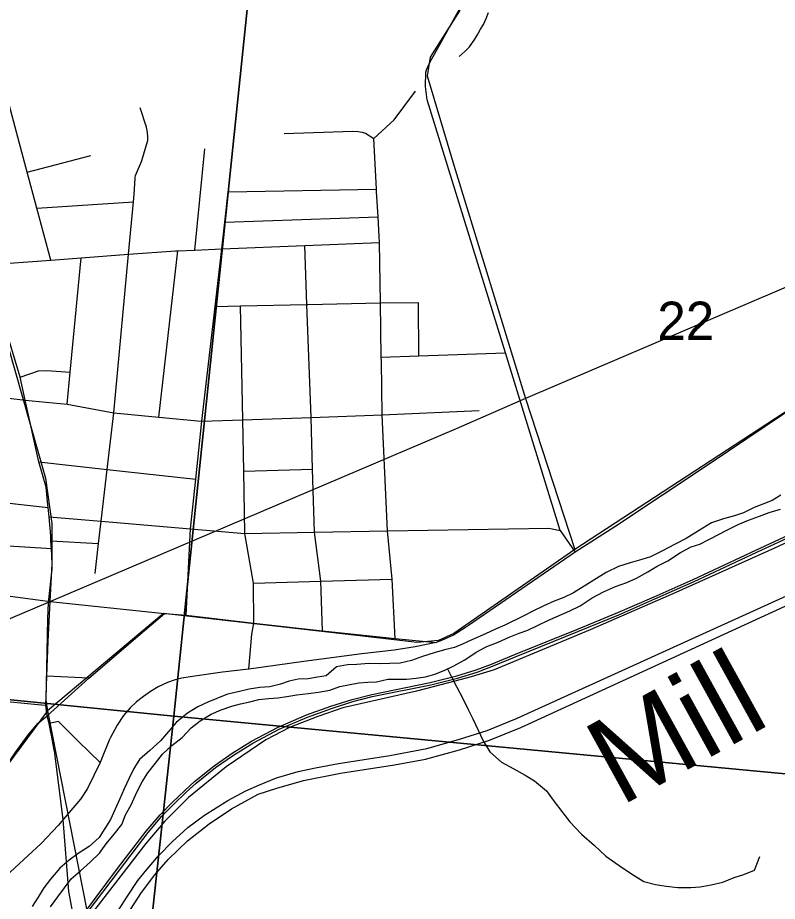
# Model space of a CAD drawing. Extents: x -8.2 to 38.5, y -0.1 to 21.9.
# Drawn here: x 5.667 to 6.498, y 17.89 to 18.858 of the extents above; entities that cross this region are included whole.
import ezdxf

# ---------------------------------------------------------------- set-up
doc = ezdxf.new("R2010")
doc.units = 0
for name, color, linetype in [('GM_X_Adjacent_County_Text', 7, 'Continuous'), ('GM_X_Airport_Location_Class_3', 7, 'Continuous'), ('GM_X_County_Road_Text', 7, 'Continuous'), ('GM_X_Minor_River', 7, 'Continuous'), ('GM_X_Minor_River_Text', 7, 'Continuous'), ('GM_X_State_Location', 7, 'Continuous'), ('GM_X_Township_Subdivision_Text', 7, 'Continuous'), ('GM_X_Township_Text', 7, 'Continuous'), ('GM_X_US_Location', 7, 'Continuous')]:
    doc.layers.add(name, color=color, linetype=linetype)

msp = doc.modelspace()

# ---------------------------------------------------------------- linework, layer by layer
at = {"layer": 'GM_X_Adjacent_County_Text'}
for points in [[(5.93961, 19.07468), (5.83799, 18.09248), (4.83948, 18.19258), (4.94575, 19.17922)], [(5.93961, 19.07468), (6.95853, 18.98963), (6.85894, 17.99642), (5.83799, 18.09248)], [(6.85894, 17.99642), (6.75364, 16.98553), (5.7325, 17.12325), (5.83799, 18.09248)]]:
    msp.add_lwpolyline(points, close=True, dxfattribs=at)
msp.add_lwpolyline([(4.75441, 17.38985), (4.83948, 18.19258), (5.83799, 18.09248), (5.7325, 17.12325), (5.03564, 17.19219)], dxfattribs=at)
at = {"layer": 'GM_X_Airport_Location_Class_3'}
for points in [[(5.70343, 18.07485), (5.7014, 18.08446), (5.69927, 18.09317), (5.69796, 18.10419), (5.69884, 18.13649), (5.70025, 18.17468), (5.70267, 18.21835), (5.70495, 18.25962), (5.704, 18.27618), (5.70351, 18.28476), (5.7032, 18.2901), (5.70136, 18.3109), (5.70045, 18.32113), (5.69985, 18.32787), (5.69824, 18.34352), (5.69005, 18.37104), (5.67517, 18.43875), (5.6697, 18.46371), (5.63265, 18.58676)], [(5.70717, 18.05558), (5.70404, 18.07196), (5.70343, 18.07485)], [(5.7594, 17.81549), (5.75592, 17.81917), (5.74934, 17.82772), (5.7386, 17.84505), (5.73114, 17.86457), (5.72675, 17.88124), (5.72302, 17.90054), (5.71691, 17.97934), (5.70735, 18.05462), (5.70717, 18.05558)]]:
    msp.add_lwpolyline(points, dxfattribs=at)
at = {"layer": 'GM_X_Minor_River'}
for points in [[(6.15032, 18.81505), (6.15695, 18.82096), (6.16163, 18.8254), (6.16757, 18.834), (6.17076, 18.83962), (6.17357, 18.84487), (6.17675, 18.85011), (6.17997, 18.8565), (6.18243, 18.86328)], [(6.5023, 18.33466), (6.49266, 18.32885), (6.48269, 18.32494), (6.4731, 18.32103), (6.46156, 18.31527), (6.45162, 18.31213), (6.43939, 18.30867), (6.42638, 18.30447), (6.4121, 18.29575), (6.39859, 18.28701), (6.38666, 18.28088), (6.37204, 18.27331), (6.35973, 18.26719), (6.35016, 18.26404), (6.33755, 18.26059), (6.32454, 18.25639), (6.31109, 18.24992), (6.29759, 18.24156), (6.27521, 18.22775), (6.26483, 18.22272), (6.25409, 18.21845), (6.24295, 18.21344), (6.23143, 18.20807), (6.22027, 18.2023), (6.20027, 18.19222), (6.18991, 18.18794), (6.17915, 18.18292), (6.16417, 18.17612), (6.15457, 18.17183), (6.14498, 18.16791), (6.13429, 18.16517), (6.12283, 18.16207), (6.1102, 18.15786), (6.09794, 18.15364), (6.08572, 18.15055), (6.07434, 18.15049), (6.06334, 18.15003), (6.05121, 18.15036), (6.03829, 18.1492), (6.02804, 18.14872), (6.01585, 18.14678), (6.00457, 18.13684), (5.99505, 18.1352), (5.98514, 18.13357), (5.97413, 18.13312), (5.96422, 18.13111), (5.95464, 18.12758), (5.94319, 18.12485), (5.93217, 18.12402), (5.92036, 18.12206), (5.90853, 18.11935), (5.8967, 18.11664), (5.87522, 18.10812), (5.86408, 18.10273), (5.85289, 18.09582), (5.84046, 18.08553), (5.83223, 18.07588), (5.82322, 18.0655), (5.81155, 18.05519), (5.80028, 18.04524), (5.79431, 18.03516), (5.78868, 18.02392), (5.78345, 18.01305), (5.77857, 18.00142), (5.77373, 17.99092), (5.76848, 17.97967), (5.76251, 17.96958), (5.75617, 17.95988), (5.74528, 17.94993)], [(5.71822, 17.90473), (5.7257, 17.9144), (5.73581, 17.92323), (5.74631, 17.93282), (5.75645, 17.94279), (5.76394, 17.95284), (5.77258, 17.96361), (5.78122, 17.97401), (5.78492, 17.98453), (5.79129, 17.99537), (5.79777, 18.01), (5.80339, 18.02086), (5.80934, 18.03057), (5.81799, 18.04134), (5.82547, 18.05101), (5.83559, 18.0606), (5.84722, 18.06939), (5.85698, 18.07976), (5.86668, 18.08747), (5.87864, 18.09473), (5.88978, 18.09974), (5.90126, 18.1036), (5.91081, 18.106), (5.92111, 18.10837), (5.93104, 18.11076), (5.94169, 18.11198), (5.95195, 18.11284), (5.96147, 18.1141), (5.97252, 18.11608), (5.98508, 18.11763), (5.99611, 18.11884), (6.00868, 18.12116), (6.01979, 18.12503), (6.03085, 18.12738), (6.04038, 18.12902), (6.05026, 18.12989), (6.05975, 18.13039), (6.07234, 18.13308), (6.0822, 18.13319), (6.09244, 18.13329), (6.10309, 18.13413), (6.11337, 18.13575), (6.12368, 18.1385), (6.13366, 18.14279), (6.14365, 18.14745), (6.15636, 18.15431), (6.16873, 18.1627), (6.18065, 18.16883), (6.19293, 18.17381), (6.20483, 18.17918), (6.21595, 18.18343), (6.22553, 18.18696), (6.23667, 18.19236), (6.24743, 18.19737), (6.27124, 18.20811), (6.28277, 18.21349), (6.29591, 18.22224), (6.30822, 18.22874), (6.32127, 18.23446), (6.33392, 18.23904), (6.34428, 18.24369), (6.35661, 18.25057), (6.36702, 18.25674), (6.37857, 18.26288), (6.39248, 18.27199), (6.40402, 18.27812), (6.41358, 18.2809), (6.42512, 18.28666), (6.44321, 18.29641), (6.45552, 18.30253), (6.46702, 18.30715), (6.47891, 18.31176), (6.48963, 18.31564), (6.50188, 18.31948)], [(6.13731, 18.14449), (6.14159, 18.13657), (6.14775, 18.12425), (6.15393, 18.11269), (6.16008, 18.09998), (6.16515, 18.08959), (6.17635, 18.06574), (6.18366, 18.05377), (6.19668, 18.04242), (6.21018, 18.03486), (6.22255, 18.0281), (6.23266, 18.02176), (6.24569, 18.0108), (6.25305, 18.00073), (6.26373, 17.98677), (6.27147, 17.97708), (6.28406, 17.96345), (6.2982, 17.95094), (6.31084, 17.93922), (6.32541, 17.92898), (6.33887, 17.9199), (6.35234, 17.91158), (6.36518, 17.90823), (6.37692, 17.90642), (6.38942, 17.90497), (6.40386, 17.905), (6.41415, 17.90589), (6.42597, 17.90789), (6.43897, 17.91099), (6.45125, 17.91602), (6.46197, 17.91918), (6.47348, 17.92384), (6.47917, 17.93892)], [(5.74528, 17.94993), (5.73331, 17.94229), (5.72324, 17.93497), (5.71314, 17.92613), (5.70295, 17.91426), (5.69585, 17.90458), (5.6895, 17.89451), (5.68276, 17.88406)], [(5.70285, 17.88389), (5.71112, 17.89468), (5.71822, 17.90473)]]:
    msp.add_lwpolyline(points, dxfattribs=at)
at = {"layer": 'GM_X_State_Location'}
for points in [[(5.77758, 17.88024), (5.78712, 17.89559), (5.79863, 17.91259), (5.80828, 17.92477), (5.82101, 17.93979), (5.83603, 17.95514), (5.85314, 17.97061), (5.87156, 17.98431), (5.89697, 18.00027), (5.91663, 18.01085), (5.93155, 18.01732), (5.95019, 18.02522), (5.97421, 18.03191), (5.99307, 18.03618), (6.01818, 18.04068), (6.07444, 18.04945), (6.11502, 18.05735), (6.14967, 18.06711), (6.18092, 18.07709), (6.21295, 18.08992), (6.51657, 18.22815)], [(6.49366, 18.20681), (6.52072, 18.21922)], [(5.75024, 17.8086), (5.75592, 17.81917), (5.78641, 17.87488), (5.80242, 17.89944), (5.81712, 17.91896), (5.83159, 17.93563), (5.85287, 17.95603), (5.87655, 17.97467), (5.90112, 17.99134), (5.93014, 18.00732), (5.95069, 18.01393), (5.97986, 18.02205), (6.02021, 18.03038), (6.07943, 18.03937), (6.11343, 18.04551), (6.15049, 18.05582), (6.18339, 18.06635), (6.21761, 18.08017), (6.49366, 18.20681)]]:
    msp.add_lwpolyline(points, dxfattribs=at)
at = {"layer": 'GM_X_Township_Subdivision_Text'}
for p, q in [((6.05974, 18.66986), (6.05669, 18.72507)), ((5.86085, 18.60307), (5.87178, 18.71378)), ((5.67743, 18.68846), (5.74703, 18.70664)), ((5.89757, 18.66673), (6.05974, 18.66986)), ((5.68803, 18.64905), (5.7937, 18.65591)), ((5.89376, 18.6337), (6.06143, 18.63934)), ((5.82139, 18.42013), (5.84218, 18.60232)), ((6.10597, 18.48713), (6.10586, 18.54549)), ((6.06604, 18.42255), (6.17227, 18.42724)), ((5.91442, 18.36093), (5.98984, 18.3632)), ((5.62311, 18.2814), (5.704, 18.27618)), ((5.70351, 18.28476), (5.75566, 18.28157)), ((5.74498, 18.13411), (5.69884, 18.13649))]:
    msp.add_line(p, q, dxfattribs=at)
for points in [[(6.12044, 18.81232), (6.12338, 18.81765), (6.15279, 18.87094), (6.1531, 18.88078), (6.15144, 18.893), (6.13467, 18.99904), (6.13099, 19.01927), (6.11813, 19.05226), (6.08483, 19.12819), (6.08404, 19.13227), (6.0842, 19.13477), (6.08477, 19.14768), (6.09534, 19.20706), (6.09829, 19.21858)], [(5.70338, 18.59204), (5.68803, 18.64905), (5.67743, 18.68846), (5.66422, 18.73755), (5.66233, 18.74455), (5.62818, 18.87142), (5.62675, 18.87487), (5.62511, 18.87714), (5.6212, 18.87997), (5.61669, 18.88162), (5.60648, 18.88304), (5.59396, 18.88377), (5.58965, 18.88366), (5.58108, 18.88183), (5.57089, 18.87958), (5.56302, 18.87704), (5.55397, 18.87266), (5.54954, 18.87021), (5.52968, 18.85273)], [(6.26095, 18.29608), (6.22512, 18.41204), (6.20089, 18.49045), (6.11529, 18.76739), (6.11338, 18.78225), (6.11376, 18.79782), (6.11439, 18.80023), (6.11701, 18.8061), (6.12044, 18.81232)], [(5.9586, 18.73075), (6.03382, 18.73309), (6.0396, 18.7327), (6.04401, 18.7322), (6.04773, 18.73101), (6.05669, 18.72507), (6.07903, 18.74559), (6.10251, 18.77708)], [(5.75182, 18.24872), (5.75566, 18.28157), (5.75853, 18.30608), (5.76517, 18.36277), (5.77244, 18.4248), (5.78841, 18.59839), (5.7937, 18.65591), (5.79446, 18.66428), (5.79552, 18.68149), (5.79559, 18.6825), (5.79605, 18.68485), (5.80267, 18.70014), (5.80939, 18.72312), (5.8095, 18.72454), (5.8095, 18.72703), (5.80917, 18.73168), (5.80789, 18.7376), (5.80125, 18.75868)], [(5.85151, 18.20332), (5.85637, 18.29783), (5.86202, 18.3521), (5.86866, 18.41573), (5.88309, 18.54112), (5.89037, 18.60425), (5.89376, 18.6337), (5.89757, 18.66673)], [(6.06502, 18.4857), (6.06405, 18.54535), (6.06298, 18.61116), (6.06261, 18.61797), (6.06143, 18.63934), (6.05992, 18.66666), (6.05974, 18.66986)], [(5.40917, 18.56943), (5.50382, 18.57678), (5.55479, 18.58074), (5.59743, 18.58405), (5.63265, 18.58676), (5.70338, 18.59204), (5.73644, 18.59451), (5.78841, 18.59839), (5.83983, 18.60222), (5.84218, 18.60232), (5.86085, 18.60307), (5.89037, 18.60425), (5.9812, 18.60788), (6.06298, 18.61116)], [(6.00063, 18.18623), (5.99898, 18.24048), (5.9918, 18.29416), (5.98984, 18.3632), (5.98824, 18.41986), (5.98361, 18.54357), (5.9812, 18.60788)], [(5.72118, 18.43437), (5.72449, 18.46915), (5.73644, 18.59451)], [(5.88309, 18.54112), (5.91101, 18.54179), (5.98361, 18.54357), (5.98474, 18.5436), (6.06405, 18.54535), (6.10586, 18.54549)], [(5.92566, 18.19461), (5.925, 18.23817), (5.91572, 18.29283), (5.91442, 18.36093), (5.91336, 18.41727), (5.91101, 18.54179)], [(6.06502, 18.4857), (6.10597, 18.48713), (6.20089, 18.49045)], [(6.06604, 18.42255), (6.06509, 18.48119), (6.06502, 18.4857)], [(5.6697, 18.46371), (5.69, 18.4708), (5.69912, 18.47131), (5.72449, 18.46915)], [(5.69005, 18.37104), (5.76517, 18.36277), (5.86202, 18.3521)], [(5.58468, 18.33385), (5.62804, 18.32908), (5.70045, 18.32113)], [(5.70136, 18.3109), (5.75853, 18.30608), (5.85637, 18.29783), (5.91572, 18.29283), (5.9918, 18.29416), (6.07192, 18.29557)], [(5.925, 18.23817), (5.99898, 18.24048), (6.07674, 18.24278)], [(5.9199, 18.14414), (5.92319, 18.18261), (5.92566, 18.19461)], [(5.7572, 18.04196), (5.73347, 18.06489), (5.71176, 18.08676), (5.7014, 18.08446)]]:
    msp.add_lwpolyline(points, dxfattribs=at)
at = {"layer": 'GM_X_Township_Text'}
for p, q in [((6.26095, 18.29608), (6.27738, 18.27229)), ((6.27738, 18.27229), (6.16054, 18.19189))]:
    msp.add_line(p, q, dxfattribs=at)
for points in [[(5.10844, 18.58693), (5.13465, 18.57717), (5.17693, 18.56101), (5.22232, 18.5463), (5.27916, 18.52905), (5.32274, 18.51248), (5.38916, 18.4907), (5.43187, 18.47635), (5.47758, 18.46235), (5.50265, 18.45866), (5.55352, 18.45276), (5.59578, 18.4472), (5.63905, 18.44318), (5.67517, 18.43875), (5.72118, 18.43437), (5.77244, 18.4248), (5.82139, 18.42013), (5.8678, 18.4157), (5.86866, 18.41573), (5.91336, 18.41727), (5.98824, 18.41986), (6.06604, 18.42255)], [(6.7285, 18.52761), (6.72012, 18.52925), (6.70911, 18.52942), (6.6948, 18.52876), (6.67853, 18.52645), (6.66142, 18.52128), (6.64433, 18.51429), (6.62864, 18.50605), (6.60652, 18.49144), (6.42485, 18.36945), (6.32078, 18.30007), (6.27738, 18.27229)], [(6.08032, 18.1777), (6.07674, 18.24278), (6.07192, 18.29557), (6.06604, 18.42255)], [(5.33643, 18.31941), (5.36508, 18.29943), (5.41209, 18.27171), (5.43148, 18.26028), (5.43538, 18.25798), (5.44854, 18.25343), (5.46628, 18.24951), (5.47497, 18.24837), (5.52594, 18.24165), (5.57394, 18.23532), (5.61776, 18.22954), (5.70267, 18.21835), (5.82759, 18.20501)], [(6.07192, 18.29557), (6.24831, 18.29868), (6.26095, 18.29608)], [(5.69927, 18.09317), (5.74498, 18.13411), (5.8057, 18.18628), (5.82759, 18.20501)], [(5.82759, 18.20501), (5.85151, 18.20332), (5.92566, 18.19461), (6.00063, 18.18623), (6.08032, 18.1777), (6.12503, 18.1734)], [(6.16054, 18.19189), (6.1572, 18.18959), (6.14388, 18.18137), (6.13082, 18.17538), (6.12503, 18.1734)], [(6.12503, 18.1734), (6.10213, 18.16855), (6.07894, 18.16509), (6.04386, 18.16091), (5.98007, 18.15236), (5.9199, 18.14414)], [(5.9199, 18.14414), (5.89108, 18.14086), (5.85593, 18.1358), (5.84677, 18.13412), (5.8394, 18.13238), (5.8311, 18.1294), (5.82066, 18.12465), (5.81244, 18.11955), (5.80488, 18.11429), (5.79715, 18.10821), (5.79025, 18.10163), (5.78269, 18.09325), (5.77578, 18.08289), (5.76852, 18.06919)], [(5.69796, 18.10419), (5.68924, 18.10518), (5.64387, 18.10928), (5.60612, 18.11187)], [(5.59834, 17.91377), (5.61428, 17.95606), (5.63121, 17.99815), (5.63976, 18.01546), (5.64277, 18.02104), (5.65504, 18.03908), (5.66441, 18.0524), (5.67894, 18.07261), (5.68957, 18.08512), (5.69927, 18.09317)], [(5.76852, 18.06919), (5.76707, 18.06645), (5.7572, 18.04196), (5.7434, 18.01334), (5.73583, 18.00184), (5.71691, 17.97934), (5.71183, 17.9734), (5.69292, 17.95334), (5.62496, 17.89079)]]:
    msp.add_lwpolyline(points, dxfattribs=at)
at = {"layer": 'GM_X_US_Location'}
for p, q in [((6.22295, 18.44036), (6.27693, 18.27497)), ((5.69953, 18.09843), (5.743, 17.87792))]:
    msp.add_line(p, q, dxfattribs=at)
for points in [[(5.77328, 19.69375), (5.81001, 19.63973), (5.8273, 19.603), (5.83162, 19.55114), (5.82731, 19.51008), (5.79924, 19.43661), (5.78844, 19.38906), (5.79708, 19.348), (5.81653, 19.31126), (5.84678, 19.26156), (5.88782, 19.22482), (5.93501, 19.18458), (6.06095, 19.08719), (6.11063, 19.05261), (6.12587, 19.03116), (6.13044, 19.0179), (6.14304, 18.97048), (6.15593, 18.89645), (6.15058, 18.86517), (6.11853, 18.81431), (6.11505, 18.79397), (6.14456, 18.69598), (6.22295, 18.44036)], [(5.51755, 18.86635), (5.56383, 18.8147), (5.57629, 18.78976), (5.58341, 18.76305), (5.59409, 18.72209), (5.63056, 18.58726), (5.69733, 18.35339), (5.70445, 18.30351), (5.70445, 18.25364), (5.70055, 18.21721)], [(7.12433, 18.84483), (7.06884, 18.8096), (6.93836, 18.74686), (6.81069, 18.69178), (6.22295, 18.44036)], [(6.94229, 18.5036), (6.86846, 18.51047), (6.732, 18.52985), (6.68928, 18.52901), (6.63654, 18.51126), (6.58371, 18.4755), (6.27693, 18.27497)], [(6.22295, 18.44036), (6.14701, 18.40736), (5.7716, 18.24726), (5.70055, 18.21721)], [(5.74126, 17.87891), (5.77634, 17.92567), (5.80777, 17.96687), (5.82312, 17.98468), (5.83615, 17.99821), (5.84988, 18.01108), (5.8607, 18.021), (5.88204, 18.03832), (5.90173, 18.05205), (5.92307, 18.06535), (5.95203, 18.08073), (5.98332, 18.09403), (6.00961, 18.10357), (6.03328, 18.11105), (6.05462, 18.11645), (6.11854, 18.12954), (6.14763, 18.13681), (6.16898, 18.14325), (6.18581, 18.14954), (6.21181, 18.16041), (6.27918, 18.18768), (6.32392, 18.20599), (6.36355, 18.22333), (6.4065, 18.24247), (6.47498, 18.27441), (6.67854, 18.36878)], [(5.74324, 17.8774), (5.77832, 17.92417), (5.8097, 17.96531), (5.82496, 17.98301), (5.8379, 17.99644), (5.85157, 18.00926), (5.86232, 18.01912), (5.88354, 18.03634), (5.9031, 18.04998), (5.92431, 18.0632), (5.9531, 18.07849), (5.98423, 18.09171), (6.0104, 18.10122), (6.03396, 18.10866), (6.05517, 18.11403), (6.11909, 18.12711), (6.14829, 18.13442), (6.16978, 18.14089), (6.18672, 18.14723), (6.21276, 18.15811), (6.28012, 18.18538), (6.32488, 18.2037), (6.36456, 18.22106), (6.40753, 18.24021), (6.47603, 18.27215), (6.67959, 18.36652)], [(6.67765, 18.36109), (6.49532, 18.27659), (6.38726, 18.22802), (6.29376, 18.18715), (6.18838, 18.14342), (6.16355, 18.13569), (6.13856, 18.12928), (6.10338, 18.11991), (6.02299, 18.10166), (5.9957, 18.09245), (5.96446, 18.08012), (5.93848, 18.06664), (5.89525, 18.03721), (5.85398, 18.00351), (5.828, 17.97753), (5.80729, 17.95304), (5.74005, 17.8664)], [(6.27693, 18.27497), (6.14445, 18.18317), (6.12775, 18.17547), (6.10431, 18.17347), (6.03839, 18.18111), (5.82675, 18.20517), (5.69953, 18.09843)], [(5.70055, 18.21721), (5.65914, 18.1997), (5.57835, 18.16166), (5.51066, 18.12721), (5.44065, 18.07343), (5.37877, 18.01424), (5.33689, 17.9566), (5.28911, 17.87309), (5.26824, 17.81194), (5.21734, 17.65871), (5.14005, 17.41698)], [(5.70055, 18.21721), (5.69967, 18.19911), (5.69801, 18.11024), (5.69953, 18.09843)], [(5.69953, 18.09843), (5.63364, 18.00993), (5.56924, 17.84642)]]:
    msp.add_lwpolyline(points, dxfattribs=at)

# ---------------------------------------------------------------- texts
at = {"layer": 'GM_X_County_Road_Text'}
msp.add_text('22', height=0.041856, rotation=0.00001, dxfattribs=at).set_placement((6.36713, 18.5047))
at = {"layer": 'GM_X_Minor_River_Text'}
msp.add_text('Mill', height=0.094702, rotation=28.82821, dxfattribs=at).set_placement((6.32663, 17.99334))

doc.saveas('drawing.dxf')
